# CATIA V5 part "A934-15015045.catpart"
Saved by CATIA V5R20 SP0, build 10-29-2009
Part number: A934-15015045
Source: Unknown
Property "A": "110.000"
Property "ARTICLENO": "A934-15015045"
Property "B": "30.000"
Property "BOMINFO": "A934-15015045"
Property "CODE": "A934-15015045"
Property "L": "150.000"
Property "L1": "127.860"
Property "LINA": "A934-15015045"
Property "NB": "A934-15015045"
Property "NBSYN": "$CODE."
Property "NN": "A934"
Property "NT": "VDI 3357 H-Type Cam Drivers, self-lubricating"
Property "SUPPLIER": "CF"
Property "T": "45.000"
Property "W": "150.000"
Bounding box of the stored display mesh (mm): x 0 to 150, y 0 to 45, z -150 to 0
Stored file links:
  C:\Users\Utente\Desktop\3D files A934\A934-15015045.catpart
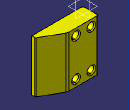
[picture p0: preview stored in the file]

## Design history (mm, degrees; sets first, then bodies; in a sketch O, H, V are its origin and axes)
Body1 "Geometry.1" (main body)
  Solid1 "A934-15015045.catpart": solid without history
